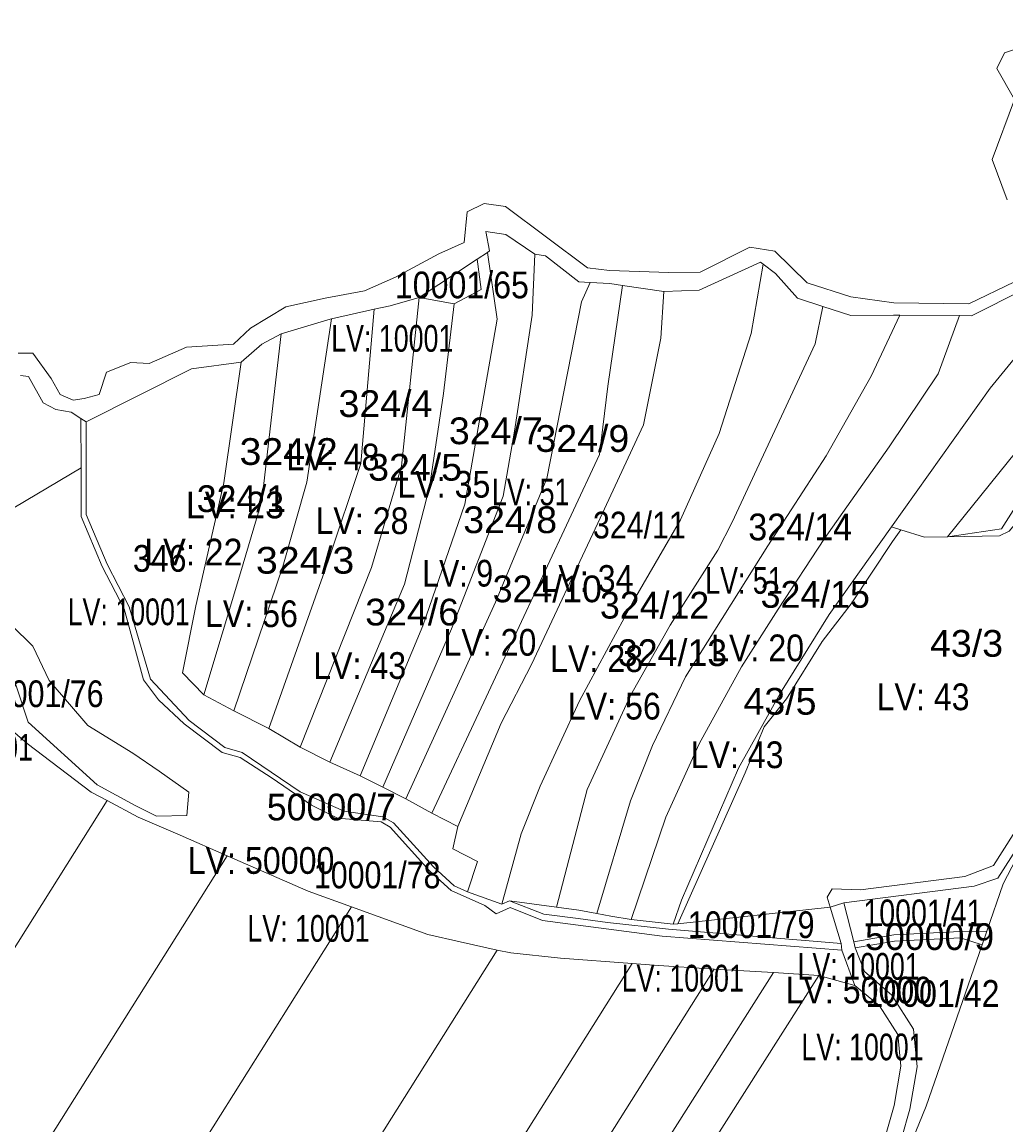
# Model space of a CAD drawing. Extents: x -713758 to -711119, y -1123067 to -1120789.
# Drawn here: x -712228.5 to -711860.1, y -1121251.9 to -1120839.2 of the extents above; entities that cross this region are included whole.
import ezdxf
from ezdxf.enums import TextEntityAlignment as Align

# ---------------------------------------------------------------- set-up
doc = ezdxf.new("R2010")
doc.units = 0
doc.header["$LTSCALE"] = 4
doc.layers.add('10', color=7, linetype='Continuous', lineweight=13)
doc.layers.add('11', color=7, linetype='Continuous')
doc.layers.add('13', color=7, linetype='Continuous')

msp = doc.modelspace()

# ---------------------------------------------------------------- linework, layer by layer
at = {"layer": '10'}
for points in [[(-711903.02, -1121028.08), (-711866.09, -1120976.19), (-711835.79, -1120939.19), (-711826.66, -1120922.21), (-711796.86, -1120879.81), (-711780.77, -1120860.87), (-711760.37, -1120839.22), (-711748.58, -1120850.82), (-711740.55, -1120860.88), (-711758.21, -1120879.11), (-711790.95, -1120924.02), (-711826.17, -1120966.22), (-711848.11, -1120994.25), (-711850.28, -1120992.52), (-711881.98, -1121031.84), (-711890.58, -1121032), (-711899.56, -1121029.17)], [(-711881.98, -1121031.84), (-711861.77, -1121028.84), (-711853.32, -1121015.43), (-711814.47, -1120973.83), (-711785.59, -1120940.28), (-711753.34, -1120899.79), (-711732.4, -1120872.48), (-711740.55, -1120860.88), (-711758.21, -1120879.11), (-711790.95, -1120924.02), (-711826.17, -1120966.22), (-711848.11, -1120994.25), (-711850.28, -1120992.52)], [(-711881.98, -1121031.84), (-711862.6, -1121031.5), (-711858.94, -1121029.71), (-711849.42, -1121018.37), (-711811.01, -1120975.09), (-711782.8, -1120941.31), (-711750.75, -1120900.66), (-711728.88, -1120875.51), (-711732.4, -1120872.48), (-711753.34, -1120899.79), (-711785.59, -1120940.28), (-711814.47, -1120973.83), (-711853.32, -1121015.43), (-711861.77, -1121028.84)], [(-712101.91, -1121121.27), (-712093.42, -1121125.55), (-712067.72, -1121066.21), (-712048.39, -1121016.57), (-712044.11, -1120992.23), (-712037.52, -1120948.93), (-712036.47, -1120926.1), (-712047.37, -1120918.69), (-712054.86, -1120917.56), (-712053.44, -1120924.83), (-712054.28, -1120925.39), (-712050.68, -1120950.4), (-712062.79, -1121019.65), (-712078.51, -1121065.16)], [(-712113.32, -1121116.16), (-712101.91, -1121121.27), (-712078.51, -1121065.16), (-712062.79, -1121019.65), (-712050.68, -1120950.4), (-712054.28, -1120925.39), (-712058.11, -1120927.93), (-712056.64, -1120939.28), (-712066.76, -1120944.65), (-712070.71, -1120978.23), (-712075.91, -1121013.27), (-712085.36, -1121049.54)], [(-712093.42, -1121125.55), (-712084.84, -1121129.91), (-712051.26, -1121056.22), (-712032.09, -1121010.01), (-712019.02, -1120943.89), (-712015.81, -1120936.68), (-712020.1, -1120936.45), (-712032.53, -1120926.69), (-712036.47, -1120926.1), (-712037.52, -1120948.93), (-712044.11, -1120992.23), (-712048.39, -1121016.57), (-712067.72, -1121066.21)], [(-712079.81, -1120942.29), (-712066.76, -1120944.65), (-712056.64, -1120939.28), (-712058.11, -1120927.93)], [(-712067.17, -1121148.53), (-712065.34, -1121140.15), (-712049.16, -1121101.57), (-712037.8, -1121079.61), (-712012.96, -1121026.77), (-711995.88, -1120989.92), (-711989.37, -1120957.46), (-711988.27, -1120940.05), (-711975.01, -1120939.58), (-711952.01, -1120929.05), (-711951.01, -1120929.82), (-711955.53, -1120955.69), (-711967.46, -1120993.21), (-711981.99, -1121025.5), (-711999.62, -1121055.78), (-712019.85, -1121093.19), (-712034.48, -1121125.11), (-712041.62, -1121142.96), (-712048.85, -1121169.24), (-712061.77, -1121164.67), (-712057.96, -1121153.35)], [(-712048.85, -1121169.24), (-712046.05, -1121168.07), (-712028.37, -1121170.42), (-712016.95, -1121126.36), (-712000.69, -1121091.18), (-711985.85, -1121064.83), (-711968.05, -1121036.86), (-711962.62, -1121026.39), (-711931.61, -1120959.63), (-711928.66, -1120945.65), (-711938.14, -1120942.56), (-711946.44, -1120933.33), (-711951.01, -1120929.82), (-711955.53, -1120955.69), (-711967.46, -1120993.21), (-711981.99, -1121025.5), (-711999.62, -1121055.78), (-712019.85, -1121093.19), (-712034.48, -1121125.11), (-712041.62, -1121142.96)], [(-712084.84, -1121129.91), (-712075.06, -1121135.16), (-712054.77, -1121091.8), (-712012.32, -1121001.01), (-712009.18, -1120975.44), (-712003.67, -1120937.78), (-712008.48, -1120937.07), (-712015.81, -1120936.68), (-712019.02, -1120943.89), (-712032.09, -1121010.01), (-712051.26, -1121056.22)], [(-712075.06, -1121135.16), (-712054.77, -1121091.8), (-712012.32, -1121001.01), (-712009.18, -1120975.44), (-712003.67, -1120937.78), (-711988.27, -1120940.05), (-711989.37, -1120957.46), (-711995.88, -1120989.92), (-712012.96, -1121026.77), (-712037.8, -1121079.61), (-712049.16, -1121101.57), (-712065.34, -1121140.15)], [(-712136.1, -1121103.58), (-712124.33, -1121110.48), (-712097.73, -1121043.26), (-712086.39, -1121005.34), (-712079.81, -1120942.29), (-712090.74, -1120945.35), (-712096.68, -1120946.69), (-712101.72, -1121004.35), (-712113.83, -1121040.54)], [(-712124.33, -1121110.48), (-712113.32, -1121116.16), (-712085.36, -1121049.54), (-712075.91, -1121013.27), (-712070.71, -1120978.23), (-712066.76, -1120944.65), (-712079.81, -1120942.29), (-712086.39, -1121005.34), (-712097.73, -1121043.26)], [(-712149.23, -1121096.93), (-712136.1, -1121103.58), (-712113.83, -1121040.54), (-712101.72, -1121004.35), (-712096.68, -1120946.69), (-712112.65, -1120950.29), (-712121.85, -1121011.41), (-712130.92, -1121042.94)], [(-712028.37, -1121170.42), (-712020.09, -1121171.52), (-712013.26, -1121172.81), (-712000.74, -1121130.6), (-711992.53, -1121109.91), (-711980.14, -1121084.25), (-711949.3, -1121035.17), (-711927.42, -1121001.52), (-711910.63, -1120971.7), (-711899.9, -1120948.9), (-711902.23, -1120948.88), (-711918.2, -1120949.05), (-711928.66, -1120945.65), (-711931.61, -1120959.63), (-711962.62, -1121026.39), (-711968.05, -1121036.86), (-711985.85, -1121064.83), (-712000.69, -1121091.18), (-712016.95, -1121126.36)], [(-712160.41, -1121090.93), (-712146.73, -1121045.29), (-712138.7, -1121018.33), (-712131.45, -1120955.86), (-712114.02, -1120950.6), (-712112.65, -1120950.29), (-712121.85, -1121011.41), (-712130.92, -1121042.94), (-712149.23, -1121096.93)], [(-712013.26, -1121172.81), (-712008.12, -1121173.78), (-712000.5, -1121174.97), (-711987.45, -1121136.76), (-711974.95, -1121109.29), (-711959.11, -1121080.5), (-711945.43, -1121058.85), (-711928.13, -1121032.49), (-711903.85, -1120998.15), (-711885.58, -1120970.79), (-711877.57, -1120949.07), (-711899.9, -1120948.9), (-711910.63, -1120971.7), (-711927.42, -1121001.52), (-711949.3, -1121035.17), (-711980.14, -1121084.25), (-711992.53, -1121109.91), (-712000.74, -1121130.6)], [(-712168.46, -1121082.71), (-712160.41, -1121090.93), (-712146.73, -1121045.29), (-712138.7, -1121018.33), (-712131.45, -1120955.86), (-712138.76, -1120959.77), (-712146.48, -1120966.42), (-712152.94, -1121011.59), (-712163.48, -1121057.63)], [(-712204.54, -1121023.49), (-712196.65, -1121042.07), (-712188.38, -1121057.96), (-712180.4, -1121085.1), (-712165.99, -1121100.52), (-712152.56, -1121110.61), (-712146.04, -1121112.56), (-712124.34, -1121127.22), (-712107.91, -1121134.42), (-712093.38, -1121136.58), (-712089.41, -1121138.83), (-712074.48, -1121155.29), (-712066.78, -1121162.46), (-712061.77, -1121164.67), (-712057.96, -1121153.35), (-712067.17, -1121148.53), (-712065.34, -1121140.15), (-712075.06, -1121135.16), (-712084.84, -1121129.91), (-712093.42, -1121125.55), (-712101.91, -1121121.27), (-712113.32, -1121116.16), (-712124.33, -1121110.48), (-712136.1, -1121103.58), (-712149.23, -1121096.93), (-712160.41, -1121090.93), (-712168.46, -1121082.71), (-712163.48, -1121057.63), (-712152.94, -1121011.59), (-712146.48, -1120966.42), (-712165.09, -1120968.98), (-712204.51, -1120988.84)], [(-712206.44, -1120987.59), (-712204.51, -1120988.84), (-712204.54, -1121023.49), (-712196.65, -1121042.07), (-712188.38, -1121057.96), (-712180.4, -1121085.1), (-712165.99, -1121100.52), (-712152.56, -1121110.61), (-712146.04, -1121112.56), (-712124.34, -1121127.22), (-712107.91, -1121134.42), (-712093.38, -1121136.58), (-712089.41, -1121138.83), (-712074.48, -1121155.29), (-712066.78, -1121162.46), (-712061.77, -1121164.67), (-712048.85, -1121169.24), (-712046.05, -1121168.07), (-712033.21, -1121173.02), (-712020.26, -1121174.59), (-712009.29, -1121176.1), (-711986.42, -1121178.67), (-711921.86, -1121183.96), (-711921.65, -1121186.45), (-711988.89, -1121181.22), (-712033.66, -1121175.38), (-712045.74, -1121170.54), (-712050.94, -1121172.89), (-712055.22, -1121169.75), (-712067.9, -1121164.16), (-712075.86, -1121156.9), (-712090.68, -1121140.41), (-712094.04, -1121138.5), (-712110.41, -1121137.09), (-712120.18, -1121132.22), (-712134.82, -1121122.17), (-712146.89, -1121114.4), (-712153.62, -1121112.53), (-712167.81, -1121101.76), (-712177.43, -1121092.8), (-712183.03, -1121085.33), (-712190.24, -1121058.71), (-712198.46, -1121042.92), (-712206.38, -1121024.27), (-712206.41, -1121006.04)], [(-711984.76, -1121176.78), (-711982.99, -1121176.59), (-711957.8, -1121120.08), (-711950.65, -1121102.96), (-711942.33, -1121092.49), (-711928.99, -1121070.99), (-711918.04, -1121056.86), (-711902.67, -1121033.6), (-711899.56, -1121029.17), (-711903.02, -1121028.08), (-711926.37, -1121060.86), (-711944.51, -1121090.23), (-711960.33, -1121118.35), (-711981.56, -1121167.74)], [(-712264.11, -1121052.71), (-712239.09, -1121076.45), (-712230.76, -1121087.53), (-712226.25, -1121101.15), (-712200.43, -1121124.56), (-712186.09, -1121132.32), (-712178.22, -1121136.29), (-712166.82, -1121136.13), (-712166.03, -1121127.39), (-712177.11, -1121119.56), (-712186.97, -1121112.79), (-712203.92, -1121102.45), (-712218.34, -1121085.52), (-712224.47, -1121072.79), (-712240.53, -1121057.06), (-712251.27, -1121051.42)], [(-712264.11, -1121052.71), (-712251.27, -1121051.42), (-712240.53, -1121057.06), (-712224.47, -1121072.79), (-712218.34, -1121085.52), (-712203.92, -1121102.45), (-712186.97, -1121112.79), (-712177.11, -1121119.56), (-712166.03, -1121127.39), (-712166.82, -1121136.13), (-712178.22, -1121136.29), (-712186.09, -1121132.32), (-712200.43, -1121124.56), (-712226.25, -1121101.15), (-712230.76, -1121087.53), (-712239.09, -1121076.45)], [(-712423.44, -1121490.64), (-712347.85, -1121370.61), (-712272.26, -1121250.57), (-712196.67, -1121130.54), (-712185, -1121136.71), (-712169.32, -1121143.39), (-712151.71, -1121151.12), (-712225.62, -1121268.49), (-712299.53, -1121385.85), (-712373.44, -1121503.22), (-712411.12, -1121493.7)], [(-711920.83, -1121168.71), (-711917.05, -1121183.35), (-711902.13, -1121180.77), (-711877.35, -1121179.44), (-711867.27, -1121179.34), (-711861.13, -1121161.65), (-711846.63, -1121133.64), (-711863.15, -1121159.5), (-711871.99, -1121162.53)], [(-712373.44, -1121503.22), (-712299.53, -1121385.85), (-712225.62, -1121268.49), (-712151.71, -1121151.12), (-712121.32, -1121164.46), (-712105.15, -1121170.27), (-712177.71, -1121285.5), (-712250.27, -1121400.74), (-712322.84, -1121515.97), (-712342.53, -1121511.25), (-712369.84, -1121504.13)], [(-712046.05, -1121168.07), (-712033.21, -1121173.02), (-712020.26, -1121174.59), (-712009.29, -1121176.1), (-711986.42, -1121178.67), (-711921.86, -1121183.96), (-711925.96, -1121170.36), (-711982.99, -1121176.59), (-711984.76, -1121176.78), (-712000.5, -1121174.97), (-712008.12, -1121173.78), (-712013.26, -1121172.81), (-712020.09, -1121171.52), (-712028.37, -1121170.42)], [(-712322.84, -1121515.97), (-712250.27, -1121400.74), (-712177.71, -1121285.5), (-712105.15, -1121170.27), (-712076.52, -1121180.56), (-712064.5, -1121183.42), (-712050.6, -1121186.42), (-712122.79, -1121301.06), (-712194.99, -1121415.7), (-712267.18, -1121530.34), (-712312.23, -1121518.51)], [(-711927.19, -1121330.54), (-711914.62, -1121305.06), (-711890.03, -1121244.84), (-711869.08, -1121184.54), (-711877.22, -1121181.83), (-711901.86, -1121183.16), (-711916.62, -1121185.66), (-711913.13, -1121194.47), (-711902.89, -1121203.34), (-711894.77, -1121216.03), (-711893.42, -1121230.17), (-711896.16, -1121245.95), (-711902.41, -1121267.94), (-711916.98, -1121303.92)], [(-711917.05, -1121183.35), (-711902.13, -1121180.77), (-711877.35, -1121179.44), (-711867.27, -1121179.34), (-711869.08, -1121184.54), (-711877.22, -1121181.83), (-711901.86, -1121183.16), (-711916.62, -1121185.66)], [(-712267.18, -1121530.34), (-712194.99, -1121415.7), (-712122.79, -1121301.06), (-712050.6, -1121186.42), (-712045.54, -1121187.51), (-712026.93, -1121189.41), (-712000.06, -1121191.51), (-712073.66, -1121308.39), (-712147.26, -1121425.26), (-712220.86, -1121542.14), (-712221.92, -1121541.87), (-712231.21, -1121539.78)], [(-712220.86, -1121542.14), (-712147.26, -1121425.26), (-712073.66, -1121308.39), (-712000.06, -1121191.51), (-711991.96, -1121192.14), (-711969.33, -1121193.53), (-712043.98, -1121312.07), (-712118.64, -1121430.62), (-712193.29, -1121549.17)], [(-712193.29, -1121549.17), (-712118.64, -1121430.62), (-712043.98, -1121312.07), (-711969.33, -1121193.53), (-711947.16, -1121194.88), (-712023.15, -1121314.53), (-712099.14, -1121434.18), (-712175.12, -1121553.83), (-712175.81, -1121553.63)], [(-712175.12, -1121553.83), (-712160.23, -1121558.04), (-712083.56, -1121437.33), (-712006.9, -1121316.63), (-711930.24, -1121195.92), (-711947.16, -1121194.88), (-712023.15, -1121314.53), (-712099.14, -1121434.18)]]:
    msp.add_lwpolyline(points, close=True, dxfattribs=at)
for points in [[(-711850.26, -1120847.24), (-711860.65, -1120850.69), (-711863.61, -1120856.54), (-711856.96, -1120868.18), (-711865.28, -1120890.65), (-711859.73, -1120905.68)], [(-711856.98, -1120936.42), (-711874.04, -1120944.64), (-711902.11, -1120944.27), (-711918.16, -1120942.01), (-711934.61, -1120936.77), (-711946.67, -1120924.9), (-711956.07, -1120923.4), (-711974.59, -1120932.77), (-711986.38, -1120932.98), (-712008.56, -1120932.22), (-712016.77, -1120931.19), (-712047.53, -1120908.21), (-712055.55, -1120907.07), (-712061.84, -1120910.17), (-712062.94, -1120921.7), (-712072.5, -1120925.98), (-712088.72, -1120934.72), (-712100.31, -1120939.77), (-712115.03, -1120942.57), (-712129.7, -1120945.76), (-712142.95, -1120953.71), (-712149.35, -1120959.79), (-712166.89, -1120960.8), (-712180.92, -1120966.99), (-712187.75, -1120966.58), (-712196.91, -1120970.25), (-712199.63, -1120978.55), (-712205.24, -1120980.13), (-712209.35, -1120980.66), (-712214.18, -1120978.58), (-712217.61, -1120972.55)], [(-712131.45, -1120955.86), (-712114.02, -1120950.6), (-712112.65, -1120950.29), (-712096.68, -1120946.69), (-712090.74, -1120945.35), (-712079.81, -1120942.29), (-712058.11, -1120927.93), (-712054.28, -1120925.39), (-712053.44, -1120924.83), (-712054.86, -1120917.56), (-712047.37, -1120918.69), (-712036.47, -1120926.1), (-712032.53, -1120926.69), (-712020.1, -1120936.45), (-712015.81, -1120936.68), (-712008.48, -1120937.07), (-712003.67, -1120937.78), (-711988.27, -1120940.05), (-711975.01, -1120939.58), (-711952.01, -1120929.05), (-711951.01, -1120929.82), (-711946.44, -1120933.33), (-711938.14, -1120942.56), (-711928.66, -1120945.65), (-711918.2, -1120949.05), (-711902.23, -1120948.88), (-711899.9, -1120948.9), (-711877.57, -1120949.07), (-711873, -1120949.11), (-711853.48, -1120939.28)], [(-711835.79, -1120939.19), (-711866.09, -1120976.19), (-711903.02, -1121028.08), (-711926.37, -1121060.86), (-711944.51, -1121090.23), (-711960.33, -1121118.35), (-711981.56, -1121167.74), (-711984.76, -1121176.78), (-712000.5, -1121174.97), (-711987.45, -1121136.76), (-711974.95, -1121109.29), (-711959.11, -1121080.5), (-711945.43, -1121058.85), (-711928.13, -1121032.49), (-711903.85, -1120998.15), (-711885.58, -1120970.79), (-711877.57, -1120949.07), (-711873, -1120949.11), (-711853.48, -1120939.28)], [(-712229.02, -1120971.51), (-712226.11, -1120971.88), (-712220.6, -1120981.66), (-712215.9, -1120984.14), (-712210.08, -1120985.22), (-712206.44, -1120987.59), (-712204.51, -1120988.84), (-712165.09, -1120968.98), (-712146.48, -1120966.42), (-712138.76, -1120959.77), (-712131.45, -1120955.86)], [(-712217.61, -1120972.55), (-712224.42, -1120963.08), (-712229.97, -1120963.16)], [(-712273.5, -1121045.77), (-712206.41, -1121006.04), (-712206.44, -1120987.59), (-712210.08, -1120985.22), (-712215.9, -1120984.14), (-712220.6, -1120981.66), (-712226.11, -1120971.88), (-712229.02, -1120971.51)], [(-712243.93, -1121094.31), (-712226.54, -1121109.19), (-712202.58, -1121127.41), (-712196.67, -1121130.54), (-712185, -1121136.71), (-712169.32, -1121143.39), (-712151.71, -1121151.12), (-712121.32, -1121164.46), (-712105.15, -1121170.27), (-712076.52, -1121180.56), (-712064.5, -1121183.42), (-712050.6, -1121186.42), (-712045.54, -1121187.51), (-712026.93, -1121189.41), (-712000.06, -1121191.51), (-711991.96, -1121192.14), (-711969.33, -1121193.53), (-711947.16, -1121194.88), (-711930.24, -1121195.92), (-711916.73, -1121199.72), (-711921.65, -1121186.45), (-711988.89, -1121181.22), (-712033.66, -1121175.38), (-712045.74, -1121170.54), (-712050.94, -1121172.89), (-712055.22, -1121169.75), (-712067.9, -1121164.16), (-712075.86, -1121156.9), (-712090.68, -1121140.41), (-712094.04, -1121138.5), (-712110.41, -1121137.09), (-712120.18, -1121132.22), (-712134.82, -1121122.17), (-712146.89, -1121114.4), (-712153.62, -1121112.53), (-712167.81, -1121101.76), (-712177.43, -1121092.8), (-712183.03, -1121085.33), (-712190.24, -1121058.71), (-712198.46, -1121042.92), (-712206.38, -1121024.27), (-712206.41, -1121006.04), (-712273.5, -1121045.77)], [(-711858.94, -1121029.71), (-711862.6, -1121031.5), (-711881.98, -1121031.84), (-711890.58, -1121032), (-711899.56, -1121029.17), (-711902.67, -1121033.6), (-711918.04, -1121056.86), (-711928.99, -1121070.99), (-711942.33, -1121092.49), (-711950.65, -1121102.96), (-711957.8, -1121120.08), (-711982.99, -1121176.59), (-711925.96, -1121170.36), (-711927.04, -1121166.6), (-711925.24, -1121163.56), (-711914.58, -1121163.89), (-711875.58, -1121158.95), (-711864.86, -1121154.76), (-711850.05, -1121131.56)], [(-712272.26, -1121250.57), (-712196.67, -1121130.54), (-712202.58, -1121127.41), (-712226.54, -1121109.19), (-712243.93, -1121094.31)], [(-711850.05, -1121131.56), (-711864.86, -1121154.76), (-711875.58, -1121158.95), (-711914.58, -1121163.89), (-711925.24, -1121163.56), (-711927.04, -1121166.6), (-711925.96, -1121170.36), (-711920.83, -1121168.71), (-711871.99, -1121162.53), (-711863.15, -1121159.5), (-711846.63, -1121133.64)], [(-711914.62, -1121305.06), (-711890.03, -1121244.84), (-711869.08, -1121184.54), (-711867.27, -1121179.34), (-711861.13, -1121161.65), (-711846.63, -1121133.64)], [(-711902.41, -1121267.94), (-711896.16, -1121245.95), (-711893.42, -1121230.17), (-711894.77, -1121216.03), (-711902.89, -1121203.34), (-711913.13, -1121194.47), (-711916.62, -1121185.66), (-711917.05, -1121183.35), (-711920.83, -1121168.71), (-711925.96, -1121170.36), (-711921.86, -1121183.96), (-711921.65, -1121186.45), (-711916.73, -1121199.72), (-711907.48, -1121207.31), (-711900.61, -1121218.04), (-711899.47, -1121229.94), (-711902.02, -1121244.62), (-711908.09, -1121265.99)], [(-712006.9, -1121316.63), (-711930.24, -1121195.92), (-711916.73, -1121199.72), (-711907.48, -1121207.31), (-711900.61, -1121218.04), (-711899.47, -1121229.94), (-711902.02, -1121244.62), (-711908.09, -1121265.99)]]:
    msp.add_lwpolyline(points, dxfattribs=at)

# ---------------------------------------------------------------- texts
at = {"layer": '11'}
for s, width, p in [('10001/65', 0.9, (-712063.84, -1120942.58)), ('324/4', 1.05, (-712092.449, -1120986.99)), ('324/7', 1.05, (-712051.13, -1120997.16)), ('324/9', 1.05, (-712018.73, -1121000.04)), ('324/2', 1.1, (-712128.67, -1121004.91)), ('324/5', 1.05, (-712081.35, -1121010.8)), ('324/8', 1.05, (-712045.76, -1121030.44)), ('324/11', 0.85, (-711997.39, -1121032.42)), ('324/14', 0.95, (-711937.17, -1121033.14)), ('346', 0.9, (-712176.961, -1121044.89)), ('324/3', 1.1, (-712122.53, -1121045.6)), ('324/6', 1.05, (-712082.459, -1121064.98)), ('43/3', 1.05, (-711874.9, -1121076.69)), ('10001/76', 0.85, (-712221.69, -1121095.54)), ('43/5', 1.05, (-711944.74, -1121098.37)), ('10001/78', 0.85, (-712095.54, -1121163.34)), ('10001/41', 0.8, (-711891.221, -1121177.52)), ('10001/79', 0.85, (-711955.52, -1121181.95)), ('10001/42', 0.9, (-711887.66, -1121207.68))]:
    msp.add_text(s, height=10, dxfattribs=dict(at, width=width)).set_placement(p, align=Align.CENTER)
for s, p in [('324/1', (-712146.37, -1121022.55)), ('324/10', (-712031.86, -1121056.3)), ('324/15', (-711931.541, -1121058.37)), ('324/12', (-711991.691, -1121062.4)), ('324/13', (-711984.98, -1121080.18)), ('50000/7', (-712112.7, -1121137.92)), ('50000/9', (-711888.73, -1121186.41))]:
    msp.add_text(s, height=10, dxfattribs=at).set_placement(p, align=Align.CENTER)
at = {"layer": '13'}
for s, width, p in [('LV: 10001 ', 0.75, (-712088.5, -1120962.58)), ('LV: 48 ', 0.9, (-712110.419, -1121006.99)), ('LV: 35 ', 0.9, (-712068.897, -1121017.16)), ('LV: 51 ', 0.75, (-712036.698, -1121020.04)), ('LV: 23 ', 0.95, (-712147.007, -1121024.91)), ('LV: 28 ', 0.9, (-712099.553, -1121030.8)), ('LV: 22 ', 0.95, (-712162.598, -1121042.55)), ('LV: 9 ', 0.85, (-712063.83, -1121050.44)), ('LV: 34 ', 0.9, (-712015.326, -1121052.42)), ('LV: 51 ', 0.75, (-711956.845, -1121053.14)), ('LV: 10001 ', 0.75, (-712187.166, -1121064.89)), ('LV: 56 ', 0.9, (-712140.934, -1121065.6)), ('LV: 20 ', 0.9, (-712051.669, -1121076.3)), ('LV: 20 ', 0.9, (-711951.45, -1121078.37)), ('LV: 43 ', 0.9, (-712100.428, -1121084.98)), ('LV: 28 ', 0.9, (-712011.734, -1121082.4)), ('LV: 43 ', 0.9, (-711889.49, -1121096.69)), ('LV: 56 ', 0.9, (-712005.09, -1121100.18)), ('LV: 10001 ', 0.75, (-712245.915, -1121115.54)), ('LV: 43 ', 0.9, (-711959.128, -1121118.37)), ('LV: 50000 ', 0.9, (-712137.327, -1121157.92)), ('LV: 10001 ', 0.75, (-712119.866, -1121183.34)), ('LV: 10001 ', 0.75, (-711913.906, -1121197.52)), ('LV: 10001 ', 0.75, (-711979.745, -1121201.95)), ('LV: 50000 ', 0.9, (-711913.558, -1121206.41)), ('LV: 10001 ', 0.75, (-711912.454, -1121227.68))]:
    msp.add_text(s, height=10, dxfattribs=dict(at, width=width)).set_placement(p, align=Align.CENTER)

doc.saveas('drawing.dxf')
